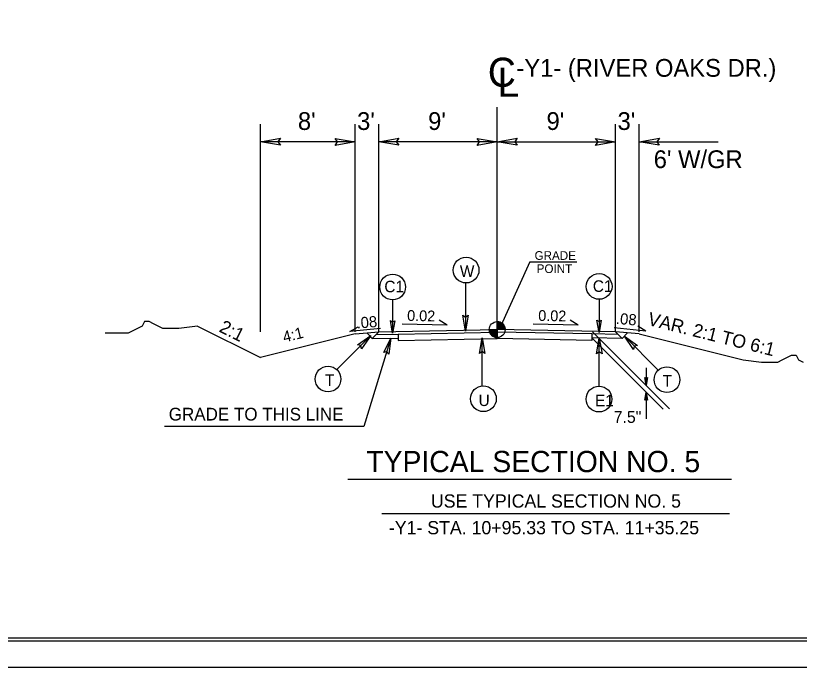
# Model space of a CAD drawing. Extents: x 1818040 to 1825768, y 638918 to 648046.
# Drawn here: x 1821216 to 1821878, y 642603 to 643153 of the extents above; entities that cross this region are included whole.
import ezdxf

# ---------------------------------------------------------------- set-up
doc = ezdxf.new("R2010")
doc.units = 0
for name, color, linetype in [('Old_Level_1', 7, 'Continuous'), ('Prop Dimension', 7, 'Continuous'), ('Prop Dimension Text', 7, 'Continuous'), ('Sheet Plot Border Inside CELL', 7, 'Continuous'), ('Sheet Plot Border Outside CELL', 7, 'Continuous'), ('Sheet Typical CELL', 7, 'Continuous'), ('Typical Grade Point Symbol CELL', 7, 'Continuous'), ('Typical ID Circle CELL', 7, 'Continuous'), ('Typical Pavement Slope CELL', 7, 'Continuous'), ('Typical Pavement Slope Information CELL', 7, 'Continuous'), ('Typical Shoulder Slope CELL', 7, 'Continuous'), ('Typical Slope Point Local CELL', 7, 'Continuous'), ('Typical Terminator CELL', 7, 'Continuous'), ('Typical Text Centerline CELL', 7, 'Continuous'), ('Typical Text General CELL', 7, 'Continuous'), ('Typical Text Grade Point CELL', 7, 'Continuous'), ('Typical Text ID Circle CELL', 7, 'Continuous'), ('Typical Text Label CELL', 7, 'Continuous')]:
    doc.layers.add(name, color=color, linetype=linetype)

msp = doc.modelspace()

# ---------------------------------------------------------------- linework, layer by layer
at = {"layer": 'Old_Level_1'}
for p, q in [((1821422.44, 642886.34), (1821422.44, 643061.79)), ((1821522.44, 642886.34), (1821516.91, 642880.81)), ((1821702.85, 642886.52), (1821768, 642821.37)), ((1821722.44, 642886.34), (1821727.97, 642880.81)), ((1821532.64, 642881.14), (1821509.85, 642806.6)), ((1821516.91, 642880.81), (1821512.23, 642885.49)), ((1821516.91, 642880.81), (1821538.92, 642881.25)), ((1821520.31, 642884.22), (1821538.92, 642884.59)), ((1821538.92, 642884.59), (1821622.44, 642886.26)), ((1821538.92, 642884.59), (1821538.92, 642879.16)), ((1821538.92, 642879.16), (1821622.44, 642880.83)), ((1821702.4, 642884.66), (1821622.44, 642886.26)), ((1821702.4, 642879.24), (1821622.44, 642880.83)), ((1821724.57, 642884.22), (1821702.4, 642884.66)), ((1821702.4, 642884.66), (1821702.4, 642879.24)), ((1821702.4, 642881.32), (1821762.52, 642821.2)), ((1821727.97, 642880.81), (1821702.4, 642881.32)), ((1821727.97, 642880.81), (1821732.65, 642885.49)), ((1821748.17, 642856.03), (1821748.17, 642841.2)), ((1821748.17, 642835.43), (1821748.17, 642813.12)), ((1821509.85, 642806.6), (1821341.44, 642806.6))]:
    msp.add_line(p, q, dxfattribs=at)
at = {"layer": 'Prop Dimension'}
for p, q in [((1821622.44, 642888.34), (1821622.44, 643076)), ((1821502.44, 642886.34), (1821502.44, 643061.79)), ((1821522.44, 642886.34), (1821522.44, 643061.79)), ((1821722.44, 642886.34), (1821722.44, 643061.79)), ((1821742.44, 642886.34), (1821742.44, 643061.79)), ((1821502.44, 643046.79), (1821422.44, 643046.79)), ((1821622.44, 643046.79), (1821522.44, 643046.79)), ((1821622.44, 643046.79), (1821722.44, 643046.79)), ((1821742.44, 643046.79), (1821808.97, 643046.79))]:
    msp.add_line(p, q, dxfattribs=at)
at = {"layer": 'Sheet Plot Border Inside CELL'}
msp.add_lwpolyline([(1822095.84, 643680.85), (1820429.34, 643680.85), (1820429.34, 642625.75), (1822095.84, 642625.75)], close=True, dxfattribs=at)
at = {"layer": 'Sheet Plot Border Outside CELL'}
msp.add_lwpolyline([(1822100.34, 643703.3), (1820416.34, 643703.3), (1820416.34, 642603.3), (1822100.34, 642603.3)], close=True, dxfattribs=at)
at = {"layer": 'Sheet Typical CELL'}
msp.add_line((1820416.34, 642603.3), (1822100.34, 642603.3), dxfattribs=at)
msp.add_lwpolyline([(1822083.34, 643678.3), (1820583.34, 643678.3), (1820583.34, 642628.3), (1822083.34, 642628.3)], close=True, dxfattribs=at)
at = {"layer": 'Typical Grade Point Symbol CELL'}
for p, q in [((1821622.44, 642888.34), (1821622.44, 642895.06)), ((1821615.73, 642888.34), (1821622.44, 642888.34)), ((1821622.43, 642881.63), (1821622.44, 642888.34)), ((1821622.44, 642888.34), (1821622.43, 642881.63)), ((1821629.15, 642888.34), (1821622.44, 642888.34))]:
    msp.add_line(p, q, dxfattribs=at)
for points in [[(1821622.5, 642895.06), (1821622.5, 642895.06), (1821622.5, 642888.34)], [(1821622.64, 642895.06), (1821622.64, 642888.34)], [(1821622.77, 642895.04), (1821622.77, 642888.34)], [(1821622.9, 642895.04), (1821622.9, 642888.34)], [(1821623.04, 642895.03), (1821623.04, 642888.34)], [(1821623.17, 642895.01), (1821623.17, 642888.34)], [(1821623.31, 642895), (1821623.31, 642888.34)], [(1821623.44, 642894.98), (1821623.44, 642888.34)], [(1821623.58, 642894.97), (1821623.58, 642888.34)], [(1821623.71, 642894.94), (1821623.71, 642888.34)], [(1821623.84, 642894.91), (1821623.84, 642888.34)], [(1821623.98, 642894.88), (1821623.98, 642888.34)], [(1821624.11, 642894.85), (1821624.11, 642888.34)], [(1821624.25, 642894.8), (1821624.25, 642888.34)], [(1821624.38, 642894.77), (1821624.38, 642888.34)], [(1821624.51, 642894.73), (1821624.51, 642888.34)], [(1821624.65, 642894.68), (1821624.65, 642888.34)], [(1821624.78, 642894.64), (1821624.78, 642888.34)], [(1821624.92, 642894.58), (1821624.92, 642888.34)], [(1821625.05, 642894.52), (1821625.05, 642888.34)], [(1821625.19, 642894.46), (1821625.19, 642888.34)], [(1821625.32, 642894.4), (1821625.32, 642888.34)], [(1821625.46, 642894.34), (1821625.46, 642888.34)], [(1821625.59, 642894.26), (1821625.59, 642888.34)], [(1821625.72, 642894.19), (1821625.72, 642888.34)], [(1821625.86, 642894.12), (1821625.86, 642888.34)], [(1821625.99, 642894.04), (1821625.99, 642888.34)], [(1821626.13, 642893.95), (1821626.13, 642888.34)], [(1821626.26, 642893.86), (1821626.26, 642888.34)], [(1821626.4, 642893.76), (1821626.4, 642888.34)], [(1821626.53, 642893.67), (1821626.53, 642888.34)], [(1821626.66, 642893.56), (1821626.66, 642888.34)], [(1821626.8, 642893.44), (1821626.8, 642888.34)], [(1821626.93, 642893.33), (1821626.93, 642888.34)], [(1821627.07, 642893.21), (1821627.07, 642888.34)], [(1821627.2, 642893.07), (1821627.2, 642888.34)], [(1821615.76, 642888.34), (1821615.76, 642887.61)], [(1821615.89, 642888.34), (1821615.89, 642886.82)], [(1821616.03, 642888.34), (1821616.03, 642886.34)], [(1821616.16, 642888.34), (1821616.16, 642885.94)], [(1821616.29, 642888.34), (1821616.29, 642885.63)], [(1821616.43, 642888.34), (1821616.43, 642885.34)], [(1821616.56, 642888.34), (1821616.56, 642885.09)], [(1821616.7, 642888.34), (1821616.7, 642884.85)], [(1821616.83, 642888.34), (1821616.83, 642884.64)], [(1821616.97, 642888.34), (1821616.97, 642884.45)], [(1821617.1, 642888.34), (1821617.1, 642884.27)], [(1821617.23, 642888.34), (1821617.23, 642884.1)], [(1821617.37, 642888.34), (1821617.37, 642883.94)], [(1821617.5, 642888.34), (1821617.5, 642883.79)], [(1821617.64, 642888.34), (1821617.64, 642883.64)], [(1821617.77, 642888.34), (1821617.77, 642883.51)], [(1821617.91, 642888.34), (1821617.91, 642883.39)], [(1821618.04, 642888.34), (1821618.04, 642883.27)], [(1821618.17, 642888.34), (1821618.17, 642883.15)], [(1821618.31, 642888.34), (1821618.31, 642883.05)], [(1821618.44, 642888.34), (1821618.44, 642882.94)], [(1821618.58, 642888.34), (1821618.58, 642882.85)], [(1821618.71, 642888.34), (1821618.71, 642882.76)], [(1821618.85, 642888.34), (1821618.85, 642882.67)], [(1821618.98, 642888.34), (1821618.98, 642882.58)], [(1821619.11, 642888.34), (1821619.11, 642882.51)], [(1821619.25, 642888.34), (1821619.25, 642882.43)], [(1821619.38, 642888.34), (1821619.38, 642882.36)], [(1821619.52, 642888.34), (1821619.52, 642882.3)], [(1821619.65, 642888.34), (1821619.65, 642882.24)], [(1821619.79, 642888.34), (1821619.79, 642882.18)], [(1821619.92, 642888.34), (1821619.92, 642882.12)], [(1821620.05, 642888.34), (1821620.05, 642882.06)], [(1821620.19, 642888.34), (1821620.19, 642882.02)], [(1821620.32, 642888.34), (1821620.32, 642881.97)], [(1821620.46, 642888.34), (1821620.46, 642881.93)], [(1821620.59, 642888.34), (1821620.59, 642881.9)], [(1821620.73, 642888.34), (1821620.73, 642881.85)], [(1821620.86, 642888.34), (1821620.86, 642881.82)], [(1821620.99, 642888.34), (1821620.99, 642881.79)], [(1821621.13, 642888.34), (1821621.13, 642881.76)], [(1821621.26, 642888.34), (1821621.26, 642881.73)], [(1821621.4, 642888.34), (1821621.4, 642881.72)], [(1821621.53, 642888.34), (1821621.53, 642881.69)], [(1821621.67, 642888.34), (1821621.67, 642881.67)], [(1821621.8, 642888.34), (1821621.8, 642881.66)], [(1821621.93, 642888.34), (1821621.93, 642881.64)], [(1821622.07, 642888.34), (1821622.07, 642881.64)], [(1821622.2, 642888.34), (1821622.2, 642881.63)], [(1821622.34, 642888.34), (1821622.34, 642881.63), (1821622.34, 642881.63)], [(1821627.33, 642892.94), (1821627.33, 642888.34)], [(1821627.47, 642892.79), (1821627.47, 642888.34)], [(1821627.6, 642892.62), (1821627.6, 642888.34)], [(1821627.74, 642892.46), (1821627.74, 642888.34)], [(1821627.87, 642892.28), (1821627.87, 642888.34)], [(1821628.01, 642892.09), (1821628.01, 642888.34)], [(1821628.14, 642891.88), (1821628.14, 642888.34)], [(1821628.27, 642891.65), (1821628.27, 642888.34)], [(1821628.41, 642891.42), (1821628.41, 642888.34)], [(1821628.54, 642891.13), (1821628.54, 642888.34)], [(1821628.68, 642890.82), (1821628.68, 642888.34)], [(1821628.81, 642890.45), (1821628.81, 642888.34)], [(1821628.95, 642889.98), (1821628.95, 642888.34)], [(1821629.08, 642889.3), (1821629.08, 642888.34)]]:
    msp.add_lwpolyline(points, dxfattribs=at)
msp.add_circle((1821622.43, 642888.34), 6.71, dxfattribs=at)
for start, end in [(359.99048, 89.99048), (179.99048, 269.99048)]:
    msp.add_arc((1821622.43, 642888.34), 6.71, start, end, dxfattribs=at)
at = {"layer": 'Typical ID Circle CELL'}
for p, q in [((1821595.68, 642927.71), (1821595.68, 642887.03)), ((1821534.13, 642913.43), (1821534.13, 642885.32)), ((1821708.55, 642913.92), (1821708.55, 642885.81)), ((1821486.96, 642854.61), (1821515.65, 642883.29)), ((1821758.52, 642854.1), (1821729.86, 642882.75)), ((1821609.74, 642840.79), (1821609.74, 642878.63)), ((1821708.64, 642840.55), (1821708.64, 642878.37))]:
    msp.add_line(p, q, dxfattribs=at)
for centre in [(1821596.19, 642938.57), (1821534.13, 642924.31), (1821708.55, 642924.8), (1821479.57, 642846.62), (1821765.87, 642846.08), (1821610.8, 642829.96), (1821708.44, 642829.68)]:
    msp.add_circle(centre, 10.88, dxfattribs=at)
at = {"layer": 'Typical Pavement Slope CELL'}
for p in [(1821522.44, 642886.34), (1821722.44, 642886.34)]:
    msp.add_line(p, (1821622.44, 642888.34), dxfattribs=at)
at = {"layer": 'Typical Pavement Slope Information CELL'}
for p, q in [((1821580.13, 642892.09), (1821573.38, 642896.17)), ((1821690.86, 642892.09), (1821684.1, 642896.17)), ((1821498.11, 642886.64), (1821505.01, 642890.81)), ((1821523.94, 642889.14), (1821498.11, 642886.64)), ((1821580.13, 642892.09), (1821542.16, 642892.85)), ((1821690.86, 642892.09), (1821652.88, 642892.85)), ((1821748.06, 642887.12), (1821721.19, 642889.71)), ((1821748.06, 642887.12), (1821741.17, 642891.28))]:
    msp.add_line(p, q, dxfattribs=at)
at = {"layer": 'Typical Shoulder Slope CELL'}
for p, q in [((1821502.44, 642884.68), (1821522.44, 642886.34)), ((1821742.44, 642884.68), (1821722.44, 642886.34))]:
    msp.add_line(p, q, dxfattribs=at)
at = {"layer": 'Typical Slope Point Local CELL'}
for p, q in [((1821369.24, 642891.28), (1821422.44, 642864.68)), ((1821502.44, 642884.68), (1821422.44, 642864.68)), ((1821742.44, 642884.68), (1821830.19, 642862.74))]:
    msp.add_line(p, q, dxfattribs=at)
for points in [[(1821369.24, 642891.28), (1821353.68, 642889.34), (1821349.79, 642889.34), (1821343.95, 642889.34), (1821340.06, 642889.34), (1821336.17, 642891.28), (1821332.28, 642893.23), (1821328.39, 642895.18), (1821324.5, 642895.18), (1821322.55, 642891.28), (1821318.66, 642889.34), (1821314.77, 642887.39), (1821310.88, 642885.45), (1821306.99, 642885.45), (1821303.1, 642885.45), (1821299.21, 642885.45), (1821295.32, 642885.45), (1821291.43, 642885.45)], [(1821830.19, 642862.74), (1821845.75, 642860.8), (1821849.64, 642860.8), (1821855.48, 642860.8), (1821859.37, 642860.8), (1821863.26, 642862.74), (1821867.15, 642864.69), (1821871.04, 642866.64), (1821874.93, 642866.64), (1821876.89, 642862.74), (1821880.78, 642860.8)]]:
    msp.add_lwpolyline(points, dxfattribs=at)
at = {"layer": 'Typical Terminator CELL'}
for points in [[(1821439.32, 643043.88), (1821422.44, 643046.79), (1821439.41, 643049.79), (1821437.25, 643046.79)], [(1821485.57, 643049.7), (1821502.44, 643046.79), (1821485.47, 643043.79), (1821487.63, 643046.79)], [(1821539.32, 643043.88), (1821522.44, 643046.79), (1821539.41, 643049.79), (1821537.25, 643046.79)], [(1821605.57, 643049.7), (1821622.44, 643046.79), (1821605.47, 643043.79), (1821607.63, 643046.79)], [(1821639.32, 643043.88), (1821622.44, 643046.79), (1821639.41, 643049.79), (1821637.25, 643046.79)], [(1821705.57, 643049.7), (1821722.44, 643046.79), (1821705.47, 643043.79), (1821707.63, 643046.79)], [(1821759.32, 643043.88), (1821742.44, 643046.79), (1821759.41, 643049.79), (1821757.25, 643046.79)], [(1821597.98, 642900.39), (1821595.68, 642887.03), (1821593.3, 642900.46), (1821595.68, 642898.75)], [(1821535.94, 642895.87), (1821534.13, 642885.32), (1821532.25, 642895.93), (1821534.13, 642894.58)], [(1821710.37, 642896.36), (1821708.55, 642885.81), (1821706.68, 642896.42), (1821708.55, 642895.07)], [(1821504.58, 642875.47), (1821515.65, 642883.29), (1821507.83, 642872.11), (1821507.36, 642875)], [(1821526.59, 642869.01), (1821532.65, 642881.13), (1821531.04, 642867.58), (1821529.26, 642869.9)], [(1821607.44, 642868.11), (1821609.74, 642881.46), (1821612.12, 642868.03), (1821609.74, 642869.74)], [(1821706.34, 642867.84), (1821708.64, 642881.2), (1821711.01, 642867.77), (1821708.64, 642869.48)], [(1821737.68, 642871.68), (1821729.86, 642882.75), (1821741.04, 642874.93), (1821738.15, 642874.46)], [(1821749.37, 642847.87), (1821748.17, 642841.2), (1821747.04, 642847.93), (1821748.22, 642847.06)], [(1821747.04, 642828.75), (1821748.17, 642835.43), (1821749.38, 642828.72), (1821748.19, 642829.57)]]:
    msp.add_lwpolyline(points, close=True, dxfattribs=at)
at = {"layer": 'Typical Text Grade Point CELL'}
for q in [(1821623.98, 642888.34), (1821689.75, 642945.44)]:
    msp.add_line((1821649.95, 642945.44), q, dxfattribs=at)
at = {"layer": 'Typical Text Label CELL'}
for p, q in [((1821496.25, 642762.04), (1821820.31, 642762.04)), ((1821524.93, 642733.2), (1821818.77, 642733.2))]:
    msp.add_line(p, q, dxfattribs=at)

# ---------------------------------------------------------------- texts
at = {"layer": 'Prop Dimension Text'}
for s, height, p in [('-Y1- (RIVER OAKS DR.)', 15, (1821638.7, 643101.74)), ("8'", 15, (1821454.13, 643056.85)), ("3'", 15, (1821504.13, 643056.85)), ("9'", 15, (1821564.13, 643056.85)), ("9'", 15, (1821664.13, 643056.85)), ("3'", 15, (1821724.13, 643056.85)), ("6' W/GR", 15, (1821754.66, 643024.65)), ('7.5"', 10, (1821720.86, 642809.58))]:
    msp.add_text(s, height=height, dxfattribs=at).set_placement(p)
at = {"layer": 'Typical Pavement Slope Information CELL'}
for p in [(1821546.32, 642895.72), (1821657.05, 642895.72)]:
    msp.add_text('0.02 ', height=9.107, rotation=358.85426, dxfattribs=at).set_placement(p)
at = {"layer": 'Typical Slope Point Local CELL'}
for s, rotation, p in [('.08', 4.76147, (1821504.04, 642889.15)), ('.08', 355.23853, (1821722.45, 642893.22)), ('4:1', 14.03624, (1821442.6, 642877.37))]:
    msp.add_text(s, height=9.373, rotation=rotation, dxfattribs=at).set_placement(p)
at = {"layer": 'Typical Text Centerline CELL'}
msp.add_text('C', height=24.6, dxfattribs=at).set_placement((1821614.51, 643093.26))
msp.add_text('L', height=24.62, rotation=359.9469, dxfattribs=at).set_placement((1821622.69, 643084.86))
at = {"layer": 'Typical Text General CELL'}
for s, height, rotation, p in [('VAR. 2:1 TO 6:1', 11.1896, 345.96376, (1821748.88, 642892.39)), ('2:1 ', 11.19, 333.43495, (1821386.77, 642886.94))]:
    msp.add_text(s, height=height, rotation=rotation, dxfattribs=at).set_placement(p)
msp.add_text('GRADE TO THIS LINE', height=10.742, dxfattribs=at).set_placement((1821345.02, 642811.6))
at = {"layer": 'Typical Text Grade Point CELL'}
for s, height, p in [('GRADE', 7.34, (1821654.04, 642947.2)), ('POINT', 7.34, (1821655.81, 642936.08)), ('-Y1- STA. 10+95.33 TO STA. 11+35.25', 11.1896, (1821530.97, 642715.57))]:
    msp.add_text(s, height=height, dxfattribs=at).set_placement(p)
at = {"layer": 'Typical Text ID Circle CELL'}
for s, height, p in [('W', 9.73, (1821590.91, 642932.79)), ('C1', 9.735, (1821527.13, 642919.85)), ('C1', 9.735, (1821703.23, 642920.2)), ('T', 9.73, (1821476.94, 642840.78)), ('T', 9.73, (1821762.2, 642840.24)), ('U', 9.73, (1821606.72, 642823.82)), ('E1', 9.735, (1821705.05, 642823.55))]:
    msp.add_text(s, height=height, dxfattribs=at).set_placement(p)
at = {"layer": 'Typical Text Label CELL'}
for s, height, p in [('TYPICAL SECTION NO. 5  ', 17.9034, (1821511.88, 642768.04)), ('USE TYPICAL SECTION NO. 5', 11.1896, (1821566.47, 642738.09))]:
    msp.add_text(s, height=height, dxfattribs=at).set_placement(p)

doc.saveas('drawing.dxf')
